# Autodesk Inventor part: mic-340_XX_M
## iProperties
Shininess: 20.0
Length Units: 11269
Angle Units: 11279
Time Units: 11290
Mass Units: 11283
Length Display Precision: 2
Angle Display Precision: 2
Part Number: mic-340_XX_M
Material: Nichtrostender Stahl - 440C
Document SubType Name: Modellieren
Description: mic 340 Sensoren
Checked By: Alves
Created: 2005-08
Designer: Ohle
Manufacturer: Standard
Standards Organization: Custom
Density: 0.0
Volumn: 0.0
Area: 0.0
PropertySet Name: Model Information
Control State: 0
Master: False
Checked Out: False
Last Check In By: Kramp
Last Check In Date: 2005-08-09
BESTELLNUMMER: mic-340/XX/M
ME: ST
Title: mic Sensoren
Author: Ohle
Comments: keine Bemerkung
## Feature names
1. Grundkörper [Revolution]
2. Messkopf mic-340 [Revolution]
3. Bohrung1 [Hole]
4. Pole [Extrusion]
5. Abrundung Pole [Fillet]
6. Verdrehsicherung [Extrusion]
